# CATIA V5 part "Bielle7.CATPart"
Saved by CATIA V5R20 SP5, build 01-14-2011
Part number: Bielle7
Bounding box of the stored display mesh (mm): x 30 to 40, y -9.974 to 157.974, z -55.891 to 9.891
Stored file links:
  E:\IAO_2010\iao\IAO_MMS_Groupe2\IAO_MMS_Groupe2\flafosse\Catia\IAO\Bielle7.CATPart
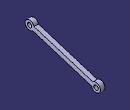
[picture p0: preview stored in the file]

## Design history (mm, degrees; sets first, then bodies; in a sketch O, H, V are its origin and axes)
Body1 (main body)
  Plane1: type Offset, RefPlane yz-plane, Offset 30
  Point1 "F": stored without definition
  Line1 "Bielle 7": stored without definition
  Sketch1 on Plane1, origin (30, 0, 0), H (0, 1, 0), V (0, 0, 1)
    arc A1 centre (0, 0) radius 10 from (9.754, 2.2043) to (6.786, -7.3451) ccw
    circle A2 centre (0, 0) radius 5
    arc A3 centre (148, -46) radius 10 from (138.246, -48.2043) to (141.214, -38.6549) ccw
    point P1 (148, -46)
    circle A4 centre (148, -46) radius 5
    reference projected point E1 (148, -46) from Point1
    line L1 (141.214, -38.6549) -> (9.754, 2.2043)
    line L2 (138.246, -48.2043) -> (6.786, -7.3451)
    reference projected line E2 (148, -46) -> (0, 0) from Line1
    radius A1 = 10
    radius A2 = 5
    radius A4 = 5
    radius A3 = 10
    coincidence: P1 E1
    tangency: L1 A2, L2 A2
    parallelism: L1 L2, L2 E2
  Pad1: profile Sketch1, direction (1, 0, 0), length 10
